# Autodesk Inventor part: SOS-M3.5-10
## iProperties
Author: Ron Crain
Shininess: 25.0
Angle Display Precision: 2
Document Length Units: 11269
Document Angle Units: 11284
Document Time Units: 11279
Document Mass Units: 11290
Document Length Units Precision: 2
Document Angle Units Precision: 2
Compacted: True
PropertySet Name: _Private Model Information
Created: 2001-09
Part Number: SOS-M3.5-10
Material: Stainless Steel, Austenitic
Description: STANDOFF, THRU HOLE THREADED, SELF CLINCH, M3.5x0.6 X 10 mm
Vendor: PENN ENG. & MFG
Document SubType Name: Modeling
Designer: Ron Crain
Control State: 0
Master: False
Checked Out: False
PropertySet Name: Design Tracking Control
Density: 7.84
Volumn: 0.17245559573138858
Area: 3.4800931280430336
PropertySet Name: Model Information
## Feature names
1. Extrusion1
2. Extrusion2
3. Revolution1
4. Revolution2
5. Rectangular Pattern1
6. Hole1
7. Chamfer3
8. Chamfer4
9. Hole3
